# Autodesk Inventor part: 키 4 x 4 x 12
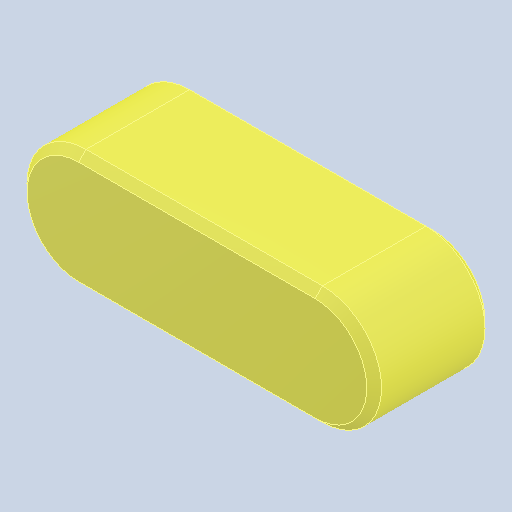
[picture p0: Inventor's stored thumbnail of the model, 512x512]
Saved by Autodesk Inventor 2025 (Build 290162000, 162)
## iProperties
Created: 2024-07
Part Number: 키 4 x 4 x 12
Material: 강철, 연강
Description: 키 및 해당 키홈
Document SubType Name: Modeling
Designer: anfro
Density: 7.85 g/cm^3
Appearance: 기본값
Author: jhkim
Sending System: Autodesk Inventor 2025
Preprocessor: ST-DEVELOPER v20
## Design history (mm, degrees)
feature "Solid1"
node "솔리드1"
